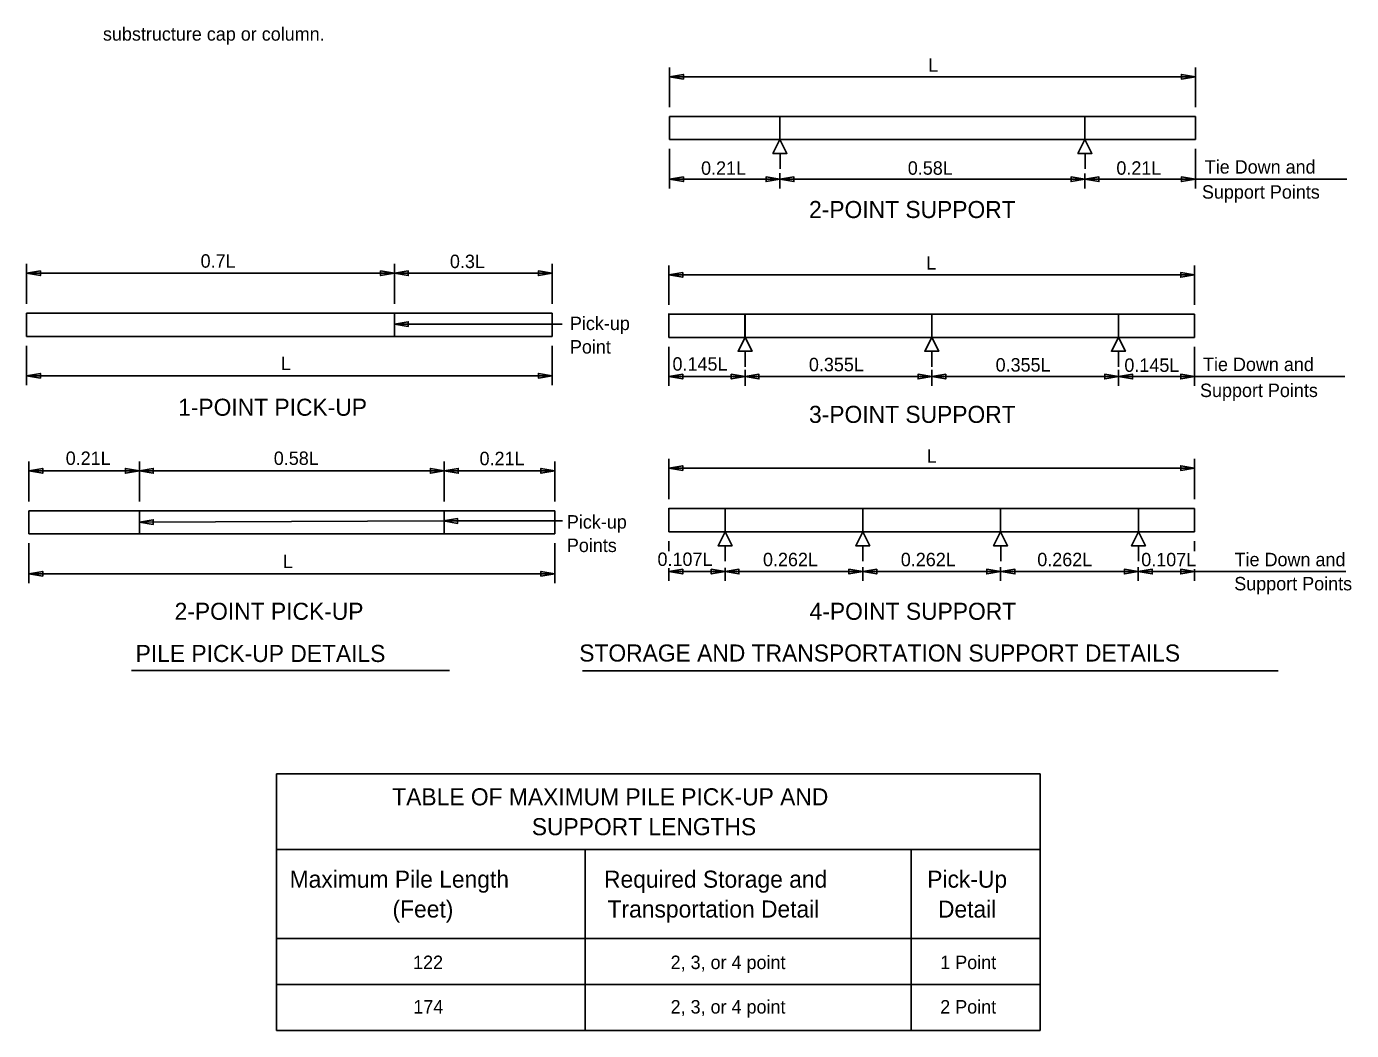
# Model space of a CAD drawing. Extents: x 120519.5 to 120592, y 120600.7 to 120635.1.
# Drawn here: x 120521.5 to 120541.38, y 120604.61 to 120619.67 of the extents above; entities that cross this region are included whole.
import ezdxf

# ---------------------------------------------------------------- set-up
doc = ezdxf.new("R2010")
doc.units = 0
for name, color, linetype in [('Dimension', 7, 'Continuous'), ('PileConc', 7, 'Continuous'), ('TextStructures', 7, 'Continuous')]:
    doc.layers.add(name, color=color, linetype=linetype)

msp = doc.modelspace()

# ---------------------------------------------------------------- linework, layer by layer
at = {"layer": 'Dimension'}
for p, q in [((120531.151, 120618.464), (120531.151, 120619.058)), ((120539.041, 120618.464), (120539.041, 120619.058)), ((120531.151, 120618.918), (120539.041, 120618.918)), ((120531.151, 120617.24), (120531.151, 120617.836)), ((120532.81, 120617.536), (120532.81, 120617.768)), ((120537.386, 120617.536), (120537.386, 120617.768)), ((120539.041, 120617.836), (120539.041, 120617.24)), ((120541.313, 120617.38), (120531.151, 120617.38)), ((120532.808, 120617.47), (120532.808, 120617.24)), ((120537.385, 120617.468), (120537.385, 120617.24)), ((120521.501, 120615.509), (120521.501, 120616.109)), ((120521.501, 120615.969), (120529.39, 120615.969)), ((120527.023, 120615.509), (120527.023, 120616.109)), ((120529.39, 120615.509), (120529.39, 120616.109)), ((120531.141, 120615.496), (120531.141, 120616.084)), ((120539.03, 120615.496), (120539.03, 120616.084)), ((120531.141, 120615.944), (120539.03, 120615.944)), ((120531.141, 120615.356), (120531.141, 120615.364)), ((120532.283, 120615.356), (120532.283, 120615.359)), ((120535.085, 120615.356), (120535.085, 120615.362)), ((120529.54, 120615.208), (120527.023, 120615.208)), ((120521.501, 120614.291), (120521.501, 120614.88)), ((120529.39, 120614.291), (120529.39, 120614.881)), ((120531.141, 120614.867), (120531.141, 120614.279)), ((120532.286, 120614.567), (120532.286, 120614.799)), ((120535.086, 120614.567), (120535.086, 120614.799)), ((120537.888, 120614.567), (120537.888, 120614.799)), ((120539.03, 120614.867), (120539.03, 120614.279)), ((120529.39, 120614.431), (120521.501, 120614.431)), ((120531.141, 120614.419), (120541.285, 120614.419)), ((120532.285, 120614.522), (120532.285, 120614.279)), ((120535.088, 120614.522), (120535.088, 120614.279)), ((120537.89, 120614.522), (120537.89, 120614.279)), ((120531.141, 120612.578), (120531.141, 120613.185)), ((120539.03, 120612.578), (120539.03, 120613.185)), ((120521.538, 120612.545), (120521.538, 120613.144)), ((120521.538, 120613.004), (120529.428, 120613.004)), ((120523.195, 120612.545), (120523.195, 120613.144)), ((120527.771, 120612.545), (120527.771, 120613.144)), ((120529.428, 120612.545), (120529.428, 120613.144)), ((120531.141, 120613.045), (120539.03, 120613.045)), ((120531.141, 120612.438), (120531.141, 120612.446)), ((120532.283, 120612.438), (120532.283, 120612.441)), ((120535.085, 120612.438), (120535.085, 120612.445)), ((120527.761, 120612.252), (120523.195, 120612.235)), ((120529.546, 120612.252), (120527.761, 120612.252)), ((120521.538, 120611.321), (120521.538, 120611.917)), ((120529.428, 120611.321), (120529.428, 120611.917)), ((120531.141, 120611.95), (120531.141, 120611.801)), ((120531.986, 120611.65), (120531.986, 120611.881)), ((120534.053, 120611.65), (120534.053, 120611.881)), ((120536.12, 120611.65), (120536.12, 120611.881)), ((120538.188, 120611.65), (120538.188, 120611.881)), ((120539.03, 120611.95), (120539.03, 120611.799)), ((120529.428, 120611.461), (120521.538, 120611.461)), ((120531.141, 120611.545), (120531.141, 120611.353)), ((120541.298, 120611.493), (120531.141, 120611.493)), ((120531.985, 120611.548), (120531.985, 120611.353)), ((120531.985, 120611.418), (120531.985, 120611.353)), ((120534.051, 120611.561), (120534.051, 120611.353)), ((120536.118, 120611.561), (120536.118, 120611.353)), ((120538.185, 120611.559), (120538.185, 120611.353)), ((120539.03, 120611.531), (120539.03, 120611.353)), ((120536.121, 120611.353), (120536.121, 120611.353)), ((120527.847, 120610.008), (120523.078, 120610.008)), ((120529.843, 120610.002), (120540.285, 120610.002)), ((120525.253, 120608.457), (120536.712, 120608.457)), ((120525.253, 120604.606), (120525.253, 120608.457)), ((120536.712, 120604.606), (120536.712, 120608.457)), ((120525.253, 120607.321), (120536.712, 120607.321)), ((120529.883, 120604.606), (120529.883, 120607.321)), ((120534.778, 120604.606), (120534.778, 120607.321)), ((120525.253, 120605.985), (120536.712, 120605.985)), ((120525.253, 120605.296), (120536.712, 120605.296)), ((120525.253, 120604.606), (120536.712, 120604.606))]:
    msp.add_line(p, q, dxfattribs=at)
for points in [[(120531.151, 120618.918), (120531.36, 120618.883), (120531.36, 120618.953)], [(120539.041, 120618.918), (120538.833, 120618.953), (120538.833, 120618.883)], [(120532.808, 120617.976), (120532.913, 120617.768), (120532.703, 120617.768)], [(120537.385, 120617.976), (120537.49, 120617.768), (120537.28, 120617.768)], [(120531.151, 120617.38), (120531.36, 120617.345), (120531.36, 120617.415)], [(120532.808, 120617.38), (120532.6, 120617.345), (120532.6, 120617.415)], [(120532.808, 120617.38), (120533.016, 120617.345), (120533.016, 120617.415)], [(120537.385, 120617.38), (120537.176, 120617.415), (120537.176, 120617.345)], [(120537.385, 120617.38), (120537.593, 120617.415), (120537.593, 120617.345)], [(120539.041, 120617.38), (120538.833, 120617.415), (120538.833, 120617.345)], [(120521.501, 120615.969), (120521.71, 120615.934), (120521.71, 120616.004)], [(120527.023, 120615.969), (120526.815, 120616.004), (120526.815, 120615.934)], [(120527.023, 120615.969), (120527.231, 120616.004), (120527.231, 120615.934)], [(120529.39, 120615.969), (120529.182, 120616.004), (120529.182, 120615.934)], [(120531.141, 120615.944), (120531.35, 120615.909), (120531.35, 120615.979)], [(120539.03, 120615.944), (120538.821, 120615.979), (120538.821, 120615.909)], [(120527.023, 120615.208), (120527.231, 120615.172), (120527.231, 120615.243)], [(120532.285, 120615.007), (120532.39, 120614.799), (120532.18, 120614.799)], [(120535.085, 120615.007), (120535.19, 120614.799), (120534.98, 120614.799)], [(120537.886, 120615.007), (120537.991, 120614.799), (120537.781, 120614.799)], [(120521.501, 120614.431), (120521.71, 120614.396), (120521.71, 120614.466)], [(120529.39, 120614.431), (120529.182, 120614.466), (120529.182, 120614.396)], [(120531.141, 120614.419), (120531.35, 120614.384), (120531.35, 120614.454)], [(120532.285, 120614.419), (120532.076, 120614.384), (120532.076, 120614.454)], [(120532.285, 120614.419), (120532.493, 120614.384), (120532.493, 120614.454)], [(120535.088, 120614.419), (120534.88, 120614.454), (120534.88, 120614.384)], [(120535.088, 120614.419), (120535.296, 120614.454), (120535.296, 120614.384)], [(120537.89, 120614.419), (120537.681, 120614.454), (120537.681, 120614.384)], [(120537.89, 120614.419), (120538.098, 120614.454), (120538.098, 120614.384)], [(120539.03, 120614.419), (120538.821, 120614.454), (120538.821, 120614.384)], [(120521.538, 120613.004), (120521.746, 120612.969), (120521.746, 120613.04)], [(120523.195, 120613.004), (120522.987, 120612.969), (120522.987, 120613.04)], [(120523.195, 120613.004), (120523.403, 120612.969), (120523.403, 120613.04)], [(120527.771, 120613.004), (120527.563, 120613.04), (120527.563, 120612.969)], [(120527.771, 120613.004), (120527.98, 120613.04), (120527.98, 120612.969)], [(120529.428, 120613.004), (120529.22, 120613.04), (120529.22, 120612.969)], [(120531.141, 120613.045), (120531.35, 120613.01), (120531.35, 120613.081)], [(120539.03, 120613.045), (120538.821, 120613.081), (120538.821, 120613.01)], [(120523.195, 120612.235), (120523.403, 120612.2), (120523.403, 120612.271)], [(120527.761, 120612.252), (120527.97, 120612.216), (120527.97, 120612.287)], [(120531.985, 120612.09), (120532.09, 120611.881), (120531.88, 120611.881)], [(120534.051, 120612.09), (120534.156, 120611.881), (120533.946, 120611.881)], [(120536.118, 120612.09), (120536.223, 120611.881), (120536.013, 120611.881)], [(120538.186, 120612.09), (120538.291, 120611.881), (120538.081, 120611.881)], [(120521.538, 120611.461), (120521.746, 120611.426), (120521.746, 120611.496)], [(120529.428, 120611.461), (120529.22, 120611.496), (120529.22, 120611.426)], [(120531.141, 120611.493), (120531.35, 120611.458), (120531.35, 120611.528)], [(120531.985, 120611.493), (120531.776, 120611.458), (120531.776, 120611.528)], [(120531.985, 120611.493), (120532.193, 120611.458), (120532.193, 120611.528)], [(120534.051, 120611.493), (120533.843, 120611.458), (120533.843, 120611.528)], [(120534.051, 120611.493), (120534.26, 120611.458), (120534.26, 120611.528)], [(120536.118, 120611.493), (120535.91, 120611.528), (120535.91, 120611.458)], [(120536.125, 120611.493), (120536.333, 120611.528), (120536.333, 120611.458)], [(120538.185, 120611.493), (120537.976, 120611.528), (120537.976, 120611.458)], [(120538.185, 120611.493), (120538.393, 120611.528), (120538.393, 120611.458)], [(120539.03, 120611.493), (120538.821, 120611.528), (120538.821, 120611.458)]]:
    msp.add_lwpolyline(points, close=True, dxfattribs=at)
at = {"layer": 'PileConc'}
for p, q in [((120531.151, 120618.324), (120539.041, 120618.324)), ((120531.151, 120617.976), (120531.151, 120618.324)), ((120532.808, 120617.976), (120532.808, 120618.324)), ((120537.385, 120618.324), (120537.385, 120617.976)), ((120539.041, 120618.324), (120539.041, 120617.976)), ((120531.151, 120617.976), (120539.041, 120617.976)), ((120521.501, 120615.369), (120529.39, 120615.369)), ((120521.501, 120615.021), (120521.501, 120615.369)), ((120527.023, 120615.369), (120527.023, 120615.021)), ((120529.39, 120615.369), (120529.39, 120615.021)), ((120531.141, 120615.356), (120539.03, 120615.356)), ((120531.141, 120615.356), (120531.141, 120615.007)), ((120532.283, 120615.007), (120532.283, 120615.356)), ((120532.285, 120615.007), (120532.285, 120615.356)), ((120535.085, 120615.356), (120535.085, 120615.007)), ((120535.233, 120615.356), (120539.03, 120615.356)), ((120537.886, 120615.356), (120537.886, 120615.007)), ((120539.03, 120615.356), (120539.03, 120615.007)), ((120521.501, 120615.021), (120529.39, 120615.021)), ((120531.141, 120615.007), (120539.03, 120615.007)), ((120521.538, 120612.405), (120529.428, 120612.405)), ((120521.538, 120612.057), (120521.538, 120612.405)), ((120523.195, 120612.057), (120523.195, 120612.405)), ((120527.771, 120612.405), (120527.771, 120612.057)), ((120529.428, 120612.405), (120529.428, 120612.057)), ((120531.141, 120612.438), (120539.03, 120612.438)), ((120531.141, 120612.09), (120531.141, 120612.438)), ((120531.985, 120612.09), (120531.985, 120612.438)), ((120534.051, 120612.09), (120534.051, 120612.438)), ((120535.233, 120612.438), (120539.03, 120612.438)), ((120536.118, 120612.09), (120536.118, 120612.438)), ((120538.186, 120612.438), (120538.186, 120612.09)), ((120539.03, 120612.438), (120539.03, 120612.09)), ((120521.538, 120612.057), (120529.428, 120612.057)), ((120531.141, 120612.09), (120539.03, 120612.09))]:
    msp.add_line(p, q, dxfattribs=at)

# ---------------------------------------------------------------- texts
at = {"layer": 'Dimension'}
for s, height, p in [('substructure cap or column.', 0.2016, (120522.649, 120619.46)), ('Pick-up ', 0.2016, (120529.656, 120615.117)), ('Point', 0.2016, (120529.656, 120614.765)), ('Pick-up ', 0.2016, (120529.61, 120612.138)), ('Points', 0.2016, (120529.61, 120611.786)), ('TABLE OF MAXIMUM PILE PICK-UP AND', 0.256, (120526.99, 120607.985)), ('SUPPORT LENGTHS', 0.256, (120529.084, 120607.537)), ('Maximum Pile Length', 0.256, (120525.45, 120606.749)), ('Required Storage and', 0.256, (120530.168, 120606.749)), ('Pick-Up', 0.256, (120535.018, 120606.749)), ('(Feet)', 0.256, (120526.994, 120606.301)), ('Transportation Detail  ', 0.256, (120530.221, 120606.301)), ('Detail', 0.256, (120535.179, 120606.3))]:
    msp.add_text(s, height=height, dxfattribs=at).set_placement(p)
at = {"layer": 'TextStructures'}
for s, height, p in [('L', 0.202, (120535.031, 120618.994)), ('0.21L', 0.2016, (120531.624, 120617.447)), ('0.58L', 0.2016, (120534.726, 120617.448)), ('0.21L', 0.2016, (120537.856, 120617.448)), ('Tie Down and', 0.2016, (120539.182, 120617.465)), ('Support Points', 0.2016, (120539.14, 120617.089)), ('2-POINT SUPPORT', 0.256, (120533.244, 120616.798)), ('0.7L', 0.2016, (120524.114, 120616.053)), ('0.3L', 0.2016, (120527.855, 120616.047)), ('L', 0.202, (120535.001, 120616.024)), ('L', 0.202, (120525.318, 120614.516)), ('0.145L', 0.2016, (120531.195, 120614.508)), ('0.355L', 0.2016, (120533.242, 120614.499)), ('0.355L', 0.2016, (120536.044, 120614.494)), ('0.145L', 0.2016, (120537.976, 120614.49)), ('Tie Down and', 0.2016, (120539.156, 120614.502)), ('Support Points', 0.2016, (120539.111, 120614.112)), ('1-POINT PICK-UP', 0.256, (120523.777, 120613.831)), ('3-POINT SUPPORT', 0.256, (120533.244, 120613.724)), ('0.21L', 0.2016, (120522.09, 120613.093)), ('0.58L', 0.2016, (120525.212, 120613.093)), ('0.21L', 0.2016, (120528.3, 120613.089)), ('L', 0.202, (120535.01, 120613.125)), ('0.107L', 0.2016, (120530.97, 120611.577)), ('0.262L', 0.2016, (120532.553, 120611.573)), ('0.262L', 0.2016, (120534.621, 120611.573)), ('0.262L', 0.2016, (120536.669, 120611.573)), ('0.107L', 0.2016, (120538.229, 120611.572)), ('Tie Down and', 0.2016, (120539.63, 120611.573)), ('L', 0.202, (120525.349, 120611.545)), ('Support Points', 0.2016, (120539.625, 120611.211)), ('2-POINT PICK-UP', 0.256, (120523.724, 120610.769)), ('4-POINT SUPPORT', 0.256, (120533.252, 120610.769)), ('PILE PICK-UP DETAILS', 0.256, (120523.139, 120610.136)), ('STORAGE AND TRANSPORTATION SUPPORT DETAILS', 0.256, (120529.796, 120610.143)), ('122', 0.2016, (120527.302, 120605.528)), ('2, 3, or 4 point', 0.2016, (120531.167, 120605.528)), ('1 Point', 0.2016, (120535.213, 120605.528)), ('174', 0.2016, (120527.306, 120604.861)), ('2, 3, or 4 point', 0.2016, (120531.167, 120604.861)), ('2 Point', 0.2016, (120535.213, 120604.861))]:
    msp.add_text(s, height=height, dxfattribs=at).set_placement(p)

doc.saveas('drawing.dxf')
